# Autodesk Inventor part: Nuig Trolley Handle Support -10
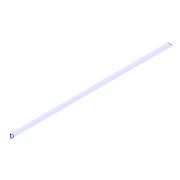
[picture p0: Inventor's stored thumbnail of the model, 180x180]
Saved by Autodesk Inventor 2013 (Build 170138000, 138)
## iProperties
Shininess: 64.0
Length Units: 11269
Angle Units: 11279
Time Units: 11290
Mass Units: 11286
Length Display Precision: 3
Angle Display Precision: 2
Created: 2002-08
Part Number: Nuig Trolley Handle Support -10
Document SubType Name: Modeling
Designer: kalamea
Density: 1 g/cm^3
Material: Generic
Density: 0.0
Volumn: 0.0
Area: 0.0
PropertySet Name: Model Information
Control State: 0
Master: False
Checked Out: False
DRAWING NUMBER: ME-12-2007-PT
Author: kalamea
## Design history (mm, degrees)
sketch "Sketch1"
  geometry: C1 r 12.7 at (0, 0); C2 r 9.525 at (0, 0); 1 further point
  constraints: 2 centre point, 2 coincident
  dimensions: "d0" = 19.05 diameter of C2; "d1" = 25.4 diameter of C1
extrude "Extrusion1" new body sketch "Sketch1" stored distance "d2" = 1058.86278; taper "d3" = 0 deg
workaxis "Work Axis2"
workplane "Work Plane3"
sketch "Sketch2"
  geometry: L1 (529.431, 12.7)-(529.431, -12.7) reference; C1 r 12.7 at (529.431, 0)
  constraints: 1 centre point, 1 midpoint
  dimensions: "d7" = 25.4 diameter of C1
extrude "Extrusion2" cut sketch "Sketch2" stored distance "d8" = 50.8; taper "d9" = 0 deg
sketch "Sketch3"
  geometry: L1 (9.525, -529.431)-(-9.525, -529.431) reference; L2 (12.7, -529.431)-(-12.7, -529.431) reference; C1 r 12.7 at (0, -529.431)
  constraints: 1 centre point, 1 midpoint
  dimensions: "d10" = 25.4 diameter of C1
extrude "Extrusion3" cut sketch "Sketch3" stored distance "d11" = 10; taper "d12" = 0 deg
body "Solid1"
other parameters: "d6" = 0
